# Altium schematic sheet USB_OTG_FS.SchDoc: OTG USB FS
size A4; Date: 01-DEC-2013; Author: A.B; CompanyName: STMicroelectronics; Organization: Microcontrollers Division; Address1: 12, Rue Jules HOROWITZ; Address2: 38019 Grenoble; Address3: FRANCE; DocumentNumber: MB1184; Revision: C-01; SheetNumber: 7; SheetTotal: 10; Project: STM32L476G-DISCO
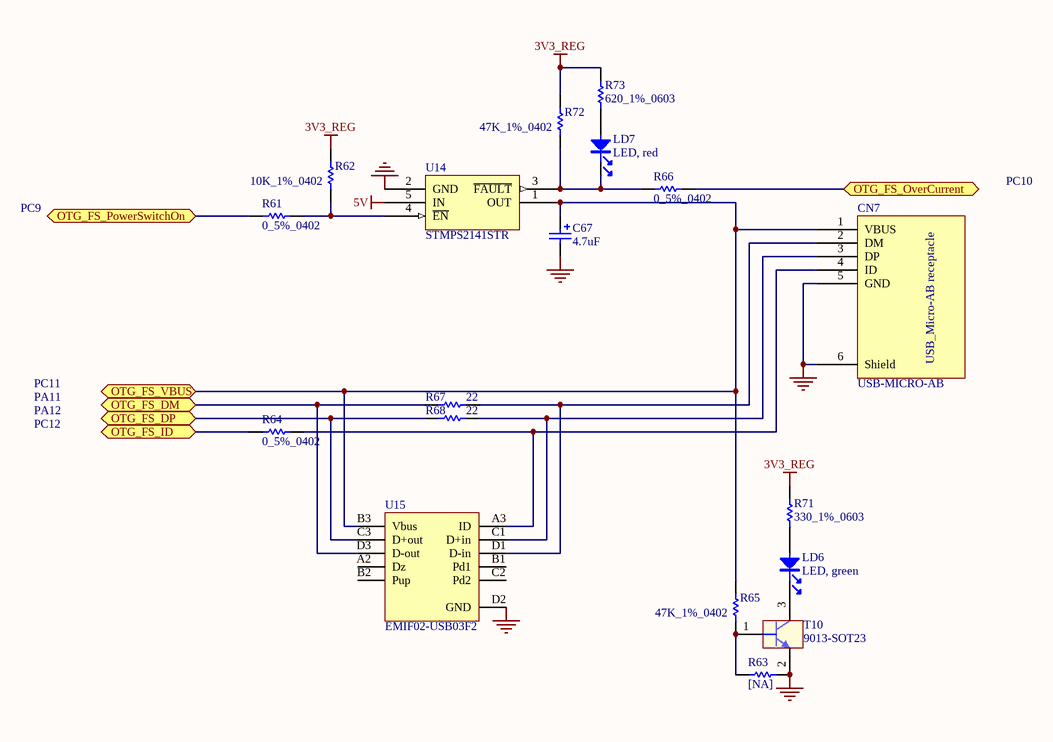
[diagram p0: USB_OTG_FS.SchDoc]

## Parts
C67  4.7uF  [TAN-A]
CN7  USB-MICRO-AB  [USB-MICRO-AB]
LD6  LED, green  [0603D]
LD7  LED, red  [0603D]
R61  0_5%_0402  [0402R]
R62  10K_1%_0402  [0402R]
R63  [NA]  [0402R]
R64  0_5%_0402  [0402R]
R65  47K_1%_0402  [0402R]
R66  0_5%_0402  [0402R]
R67  22  [0402R]
R68  22  [0402R]
R71  330_1%_0603  [0603R]
R72  47K_1%_0402  [0402R]
R73  620_1%_0603  [0603R]
T10  9013-SOT23  [SOT23]
U14  STMPS2141STR  [SOT23-5L]
U15  EMIF02-USB03F2  [Flip Chip]

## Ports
OTG_FS_DM, OTG_FS_DP, OTG_FS_ID, OTG_FS_OverCurrent, OTG_FS_PowerSwitchOn, OTG_FS_VBUS

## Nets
3V3_REG: R62.2 R71.2 R72.2 R73.2
5V: U14.5(IN)
GND: C67.2 CN7.5(GND) CN7.6(Shield) R63.2 T10.2(E) U14.2(GND) U15.D2(GND)
OTG_FS_DM: R67.2 U15.D3(D-out) ; port OTG_FS_DM
OTG_FS_DP: R68.2 U15.C3(D+out) ; port OTG_FS_DP
OTG_FS_ID: R64.1 ; port OTG_FS_ID
OTG_FS_OverCurrent: R66.2 ; port OTG_FS_OverCurrent
OTG_FS_PowerSwitchOn: R61.1 ; port OTG_FS_PowerSwitchOn
OTG_FS_VBUS: C67.1 CN7.1(VBUS) R65.2 U14.1(OUT) U15.B3(Vbus) ; port OTG_FS_VBUS
NetCN7_2: CN7.2(DM) R67.1 U15.D1(D-in)
NetCN7_3: CN7.3(DP) R68.1 U15.C1(D+in)
NetCN7_4: CN7.4(ID) R64.2 U15.A3(ID)
NetLD6_1: LD6.1 R71.1
NetLD6_2: LD6.2 T10.3(C)
NetLD7_1: LD7.1 R73.1
NetLD7_2: LD7.2 R66.1 R72.1 U14.3(~{FAULT})
NetR61_2: R61.2 R62.1 U14.4(~{EN})
NetR63_1: R63.1 R65.1 T10.1(B)

Not connected (* = marked no-connect by the designer): U15 A2(Dz) B1(Pd1) B2(Pup) C2(Pd2)

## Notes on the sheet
- PC9
- PC10
- PC11
- PC12
- PA11
- PA12

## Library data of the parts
C67 = Cap_4.7uF_POL_10%_TANA: Polarized Capacitor,4.7uF,16V,10%,typeA,AVX; Manuf_Part_1: TAJA475K016R
CN7 = USB-MICRO-AB: USB-MICRO-AB, 47590-0001, SMT, MOLEX; Ref St: xxxxxxx
LD6 = LED_green: LED, green, 0603; Manuf_1: everlight; Manuf_Part_1: 19-213SYGC/S530-E2/TR8; Description: LED,green,0603,19-213SYGC/S530-E2/TR8,everlight; ECCN_US/EU: EAR99/NEC
LD7 = LED_red: LED, red, 0603; Manuf_1: everlight; Manuf_Part_1: 19-213-R6C-AP1Q2B/3T; Description: LED,red,0603,19-213-R6C-AP1Q2B/3T,everlight; ECCN_US/EU: EAR99/NEC
R61 R64 R66 = Res_0_5%_0402: Resistor,0,0402,5%,YAGEO; Manuf_Part_1: RC0402JR-070RL; Value: 0; Order: 2363467
R62 = Res_10K_1%_0402: Resistor,10K,0402,1%,YAGEO; Manuf_Part_1: RC0402FR-0710KL
R63 = Res_NA_0402: Resistor,[NA],0402; Fitted: NO
R65 R72 = Res_47K_1%_0402: Resistor,47K,0402,1%,YAGEO; Manuf_Part_1: RC0402FR-0747KL; Order: 9239430
R67 R68 = Res1: Resistor; Value: 1K
R71 = Res_330_1%_0603: Resistor,330,0603,1%,YAGEO; Manuf_Part_1: RT0603FRE07330RL; Value: 330; Order: 1500622RL
R73 = Res_620_1%_0603: Resistor,620,0603,1%,VISHAY; Manuf_Part_1: CRCW0603620RFKEA; Manuf_1: VISHAY DRALORIC; Value: 620; Order: 2122341
T10 = 9013-SOT23: NPN Bipolar Transistor; Manuf_1: NXP; Manuf_Part_1: BSR14; Description: NPN Bipolar Transistor, SOT-23 Footprint; Order: 1081310; ECCN_US/EU: EAR99/NEC
U14 = STMPS2141STR: Enhanced single channel power switches; Manuf_1: STM; Provided: ST; ECCN_US/EU: EAR99/NEC; Ref St: 9159003
U15 = EMIF02-USB03F2: 2-line IPAD, EMI filter including ESD protection; Manuf_1: STM; Provided: ST; ECCN_US/EU: EAR99/NEC; Ref St: 9179037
